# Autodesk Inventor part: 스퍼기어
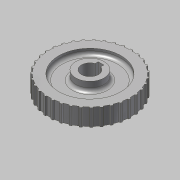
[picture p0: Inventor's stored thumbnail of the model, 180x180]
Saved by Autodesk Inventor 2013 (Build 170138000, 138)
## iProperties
Created: 2013-08
Part Number: 스퍼기어
Material: 강
Document SubType Name: Modeling
Designer: 한국산업디자인학원
Categories: <?xml version="1.0" encoding="UTF-16"?> <MemberInstance><Categories><FamilyTemplate><FamilyTemplateParameter ValueType="xs:double" Id="1" ObjectReferenceKey="da
Density: 1 g/cm^3
CustomPartVersion: 1
Author: 한국산업디자인학원
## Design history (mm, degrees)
sketch "Sketch1"
  geometry: C1 r 37 at (0, 0)
  constraints: 1 centre point
  dimensions: "d0" = 74 diameter of C1 (= da_da)
extrude "Extrusion1" new body sketch "Sketch1" distance "d1" = 15 (= da_b); taper "d2" = 0 deg
workplane "Work Plane2"
feature "피치 지름" dims "d4" = 10, "d5" = 0
workplane "Work Plane8"
workplane "Work Plane9"
feature "스퍼 기어" dims "da_b" = 15, "da_d" = 70, "da_aw" = 70, "da_da" = 74, "da_df" = 65, "da_dw" = 70, angle "da_beta" = 0 deg, "da_lefttooth" = 0, "da_righttooth" = 0
sketch "스케치3"
  geometry: L1 (0.729, 15)-(-0.729, 15) reference; L2 (0.729, 0)-(0.729, 15) reference; L3 (-0.729, 0)-(0.729, 0) reference; L4 (-0.729, 0)-(-0.729, 15) reference; L5 (0, 18)-(0, -13); L6 (35.879, 0)-(35.879, 15) reference; L7 (26.163, 15)-(21.927, 15) reference; L8 (26.163, 0)-(26.163, 15) reference; L9 (21.927, 0)-(26.163, 0) reference; L10 (21.927, 0)-(21.927, 15) reference; L11 (27.5, 15)-(27.5, 10); L12 (27.5, 10)-(12.5, 10); L13 (12.5, 10)-(12.5, 18); L14 (12.5, 18)-(7.5, 18); L15 (7.5, 18)-(7.5, -13); L16 (7.5, -13)-(12.5, -13); L17 (12.5, -13)-(12.5, 5); L18 (12.5, 5)-(27.5, 5); L19 (27.5, 5)-(27.5, 0); L20 (27.5, 15)-(35.879, 15); L21 (27.5, 0)-(35.879, 0); L22 (35.879, 0)-(35.879, 15); 7 further points
  constraints: 26 end point, 7 parallel, 6 midpoint, 4 perpendicular, 3 vertical alignment, 2 collinear, 2 horizontal alignment, 2 point on line
  dimensions: "d49" = 31 distance of L5.start L5.end; "d51" = 3 vertical distance of L1.end L5.start; "d52" = 25 diameter of L17 L5; "d53" = 5 distance of L11.start L11.end; "d54" = 55 diameter of L11 L5; "d55" = 15 diameter of L15 L5
revolve "회전1" sketch "스케치3" stored, may be unused: angle "d56" = 90 deg
sketch "스케치4"
  geometry: L1 (-7.5, 18)-(7.5, 18) reference; L2 (-7.5, -13)-(7.5, -13) reference; L3 (0, 18)-(0, -13); L4 (16.705, 15)-(16.705, 0) reference; L5 (16.705, 15)-(20.045, 15) reference; L6 (20.045, 0)-(20.045, 15) reference; L7 (16.705, 0)-(20.045, 0) reference; L8 (27.5, 15)-(27.5, 10); L9 (27.5, 10)-(12.5, 10); L10 (12.5, 10)-(12.5, 15); L11 (12.5, 15)-(27.5, 15); L12 (12.5, 18)-(12.5, 15) reference; L13 (27.5, 5)-(12.5, 5); L14 (12.5, 5)-(12.5, 0); L15 (12.5, 0)-(27.5, 0); L16 (27.5, 0)-(27.5, 5); 6 further points
  constraints: 18 end point, 7 midpoint, 4 parallel, 3 perpendicular, 3 vertical alignment, 2 horizontal alignment, 1 collinear, 1 horizontal
  dimensions: "d57" = 5 distance of L8.start L8.end; "d59" = 55 diameter of L8 L3
revolve "회전2" sketch "스케치4" stored, may be unused: angle "d60" = 90 deg
sketch "스케치5"
  geometry: C1 r 7.5 at (0, 0) reference; C2 r 12.5 at (0, 0) reference; C3 r 7.5 at (0, 0)
  constraints: 1 centre point, 1 coincident, 1 concentric
extrude "돌출2" cut sketch "스케치5" distance "d61" = 47.25; taper "d62" = 0 deg
sketch "스케치6"
  geometry: L1 (-2.5, 9.8)-(2.5, 9.8); L2 (2.5, 9.8)-(2.5, 7.071); L3 (-2.5, 7.071)-(-2.5, 9.8); L4 (0, 9.8)-(0, -7.5); C1 r 12.5 at (0, 0) reference; A1 r 7.5 centre (0, 0) between (0, -7.5) and (-2.5, 7.071) reference; A2 r 7.5 centre (0, 0) between (-2.5, 7.071) and (2.5, 7.071)
  constraints: 8 end point, 6 point on circle, 2 parallel, 1 centre point, 1 coincident, 1 horizontal, 1 midpoint, 1 perpendicular
  dimensions: "d63" = 5 distance of L1.start L1.end; "d65" = 17.3 distance of L4.start L4.end; "d66" = 2.72893 distance of L3.start L1.start
extrude "돌출3" cut sketch "스케치6" stored distance "d67" = 47.25; taper "d68" = 0 deg
fillet "모깎기1" dims "d69" = 3
fillet "모깎기2" dims "d70" = 3
body "Solid1"
sketch "Sketch2"
  geometry: C1 r 37 at (0, 0) reference; C2 r 35 at (0, 0)
  constraints: 1 centre point, 1 coincident
  dimensions: "d3" = 70 diameter of C2 (= da_dw)
body "Srf1"
node "투영된 루프1"
node "투영된 루프2"
node "투영된 루프3"
other parameters: "d17" = 0, "d34" = 0.8976 (computed from da_z), "d39" = 0, "d41" = 0, "d47" = 0, "d48" = 0
